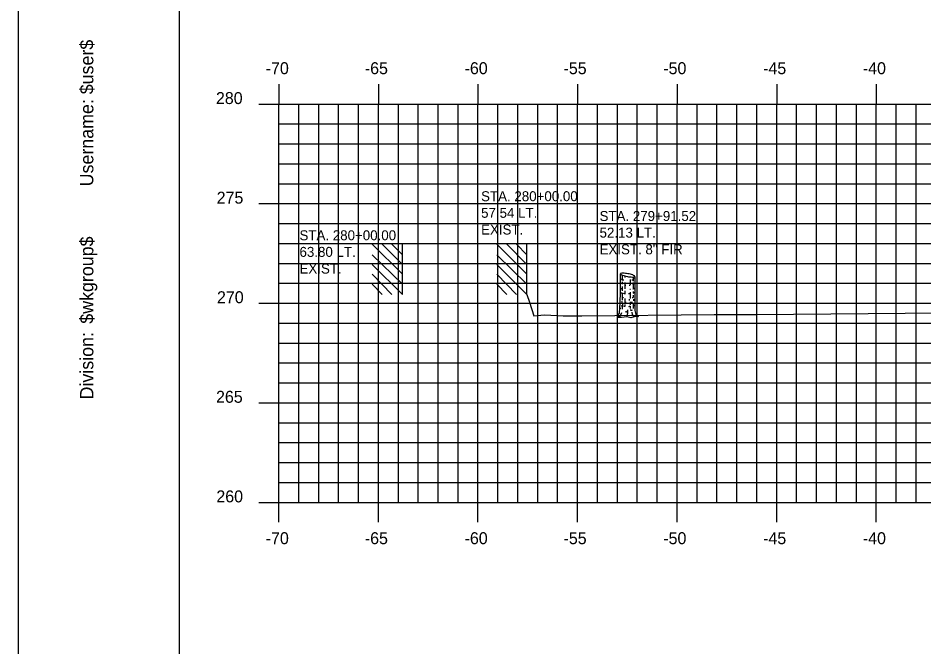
# Model space of a CAD drawing. Extents: x 855121 to 855291, y 366268 to 366378.
# Drawn here: x 855121.35 to 855166.83, y 366299.98 to 366331.55 of the extents above; entities that cross this region are included whole.
import ezdxf

# ---------------------------------------------------------------- set-up
doc = ezdxf.new("R2010")
doc.units = 0
for name, color, linetype in [('BORDER', 7, 'Continuous'), ('D_Text_Monospaced', 7, 'Continuous'), ('H_V ANNOTATION', 7, 'Continuous'), ('MAJOR', 7, 'Continuous'), ('MINOR', 7, 'Continuous'), ('PLOT BOUNDARY', 7, 'Continuous'), ('S_Buildings', 7, 'Continuous'), ('S_Roadway_Centerline', 7, 'Continuous'), ('S_Trees_Conifer_NonPay', 7, 'Continuous')]:
    doc.layers.add(name, color=color, linetype=linetype)

msp = doc.modelspace()

# ---------------------------------------------------------------- linework, layer by layer
at = {"layer": 'BORDER'}
msp.add_line((855129.442, 366376.236), (855129.442, 366271.236), dxfattribs=at)
at = {"layer": 'MAJOR'}
for p, q in [((855134.442, 366328.238), (855134.442, 366327.236)), ((855139.442, 366328.238), (855139.442, 366327.236)), ((855144.442, 366328.238), (855144.442, 366327.236)), ((855149.442, 366328.238), (855149.442, 366327.236)), ((855154.442, 366328.238), (855154.442, 366327.236)), ((855159.442, 366328.238), (855159.442, 366327.236)), ((855164.442, 366328.238), (855164.442, 366327.236)), ((855133.44, 366327.236), (855134.442, 366327.236)), ((855134.442, 366327.236), (855274.442, 366327.236)), ((855134.442, 366307.236), (855134.442, 366327.236)), ((855134.442, 366307.236), (855134.442, 366327.236)), ((855134.442, 366327.236), (855274.442, 366327.236)), ((855139.442, 366307.236), (855139.442, 366327.236)), ((855144.442, 366307.236), (855144.442, 366327.236)), ((855149.442, 366307.236), (855149.442, 366327.236)), ((855154.442, 366307.236), (855154.442, 366327.236)), ((855159.442, 366307.236), (855159.442, 366327.236)), ((855164.442, 366307.236), (855164.442, 366327.236)), ((855133.44, 366322.236), (855134.442, 366322.236)), ((855134.442, 366322.236), (855274.442, 366322.236)), ((855133.44, 366317.236), (855134.442, 366317.236)), ((855134.442, 366317.236), (855274.442, 366317.236)), ((855133.44, 366312.236), (855134.442, 366312.236)), ((855134.442, 366312.236), (855274.442, 366312.236)), ((855133.44, 366307.236), (855134.442, 366307.236)), ((855134.442, 366307.236), (855274.442, 366307.236)), ((855134.442, 366307.236), (855274.442, 366307.236)), ((855134.442, 366306.234), (855134.442, 366307.236)), ((855139.442, 366306.234), (855139.442, 366307.236)), ((855144.442, 366306.234), (855144.442, 366307.236)), ((855149.442, 366306.234), (855149.442, 366307.236)), ((855154.442, 366306.234), (855154.442, 366307.236)), ((855159.442, 366306.234), (855159.442, 366307.236)), ((855164.442, 366306.234), (855164.442, 366307.236))]:
    msp.add_line(p, q, dxfattribs=at)
at = {"layer": 'MINOR'}
for p, q in [((855135.442, 366307.236), (855135.442, 366327.236)), ((855136.442, 366307.236), (855136.442, 366327.236)), ((855137.442, 366307.236), (855137.442, 366327.236)), ((855138.442, 366307.236), (855138.442, 366327.236)), ((855140.442, 366307.236), (855140.442, 366327.236)), ((855141.442, 366307.236), (855141.442, 366327.236)), ((855142.442, 366307.236), (855142.442, 366327.236)), ((855143.442, 366307.236), (855143.442, 366327.236)), ((855145.442, 366307.236), (855145.442, 366327.236)), ((855146.442, 366307.236), (855146.442, 366327.236)), ((855147.442, 366307.236), (855147.442, 366327.236)), ((855148.442, 366307.236), (855148.442, 366327.236)), ((855150.442, 366307.236), (855150.442, 366327.236)), ((855151.442, 366307.236), (855151.442, 366327.236)), ((855152.442, 366307.236), (855152.442, 366327.236)), ((855153.442, 366307.236), (855153.442, 366327.236)), ((855155.442, 366307.236), (855155.442, 366327.236)), ((855156.442, 366307.236), (855156.442, 366327.236)), ((855157.442, 366307.236), (855157.442, 366327.236)), ((855158.442, 366307.236), (855158.442, 366327.236)), ((855160.442, 366307.236), (855160.442, 366327.236)), ((855161.442, 366307.236), (855161.442, 366327.236)), ((855162.442, 366307.236), (855162.442, 366327.236)), ((855163.442, 366307.236), (855163.442, 366327.236)), ((855165.442, 366307.236), (855165.442, 366327.236)), ((855166.442, 366307.236), (855166.442, 366327.236)), ((855134.442, 366326.236), (855274.442, 366326.236)), ((855134.442, 366326.236), (855135.444, 366326.236)), ((855134.442, 366325.236), (855274.442, 366325.236)), ((855134.442, 366325.236), (855135.444, 366325.236)), ((855134.442, 366324.236), (855274.442, 366324.236)), ((855134.442, 366324.236), (855135.444, 366324.236)), ((855134.442, 366323.236), (855274.442, 366323.236)), ((855134.442, 366323.236), (855135.444, 366323.236)), ((855134.442, 366321.236), (855274.442, 366321.236)), ((855134.442, 366321.236), (855135.444, 366321.236)), ((855134.442, 366320.236), (855274.442, 366320.236)), ((855134.442, 366320.236), (855135.444, 366320.236)), ((855134.442, 366319.236), (855274.442, 366319.236)), ((855134.442, 366319.236), (855135.444, 366319.236)), ((855134.442, 366318.236), (855274.442, 366318.236)), ((855134.442, 366318.236), (855135.444, 366318.236)), ((855134.442, 366316.236), (855274.442, 366316.236)), ((855134.442, 366316.236), (855135.444, 366316.236)), ((855134.442, 366315.236), (855274.442, 366315.236)), ((855134.442, 366315.236), (855135.444, 366315.236)), ((855134.442, 366314.236), (855274.442, 366314.236)), ((855134.442, 366314.236), (855135.444, 366314.236)), ((855134.442, 366313.236), (855274.442, 366313.236)), ((855134.442, 366313.236), (855135.444, 366313.236)), ((855134.442, 366311.236), (855274.442, 366311.236)), ((855134.442, 366311.236), (855135.444, 366311.236)), ((855134.442, 366310.236), (855274.442, 366310.236)), ((855134.442, 366310.236), (855135.444, 366310.236)), ((855134.442, 366309.236), (855274.442, 366309.236)), ((855134.442, 366309.236), (855135.444, 366309.236)), ((855134.442, 366308.236), (855274.442, 366308.236)), ((855134.442, 366308.236), (855135.444, 366308.236))]:
    msp.add_line(p, q, dxfattribs=at)
at = {"layer": 'PLOT BOUNDARY'}
msp.add_lwpolyline([(855121.349, 366268.177), (855291.349, 366268.177), (855291.349, 366378.177), (855121.349, 366378.177)], close=True, dxfattribs=at)
at = {"layer": 'S_Buildings'}
for p, q in [((855140.644, 366318.687), (855139.135, 366320.196)), ((855140.644, 366319.179), (855139.627, 366320.196)), ((855140.644, 366319.671), (855140.119, 366320.196)), ((855140.644, 366317.67), (855140.644, 366320.196)), ((855146.902, 366318.688), (855145.393, 366320.197)), ((855146.902, 366319.18), (855145.885, 366320.197)), ((855146.902, 366319.672), (855146.377, 366320.197)), ((855146.902, 366317.671), (855146.902, 366320.197)), ((855140.644, 366318.194), (855139.135, 366319.671)), ((855146.902, 366318.195), (855145.393, 366319.672)), ((855140.644, 366317.67), (855139.135, 366319.179)), ((855146.902, 366317.671), (855145.393, 366319.18)), ((855140.119, 366317.67), (855139.135, 366318.687)), ((855146.377, 366317.671), (855145.393, 366318.688)), ((855139.627, 366317.67), (855139.135, 366318.194)), ((855145.885, 366317.671), (855145.393, 366318.195))]:
    msp.add_line(p, q, dxfattribs=at)
at = {"layer": 'S_Roadway_Centerline'}
msp.add_lwpolyline([(855146.902, 366317.671), (855147.024, 366317.289), (855147.254, 366316.598), (855147.777, 366316.658), (855148.726, 366316.597), (855149.663, 366316.602), (855156.3, 366316.664), (855158.414, 366316.671), (855184.618, 366316.907), (855186.136, 366316.886), (855188.09, 366316.761), (855188.288, 366316.664), (855188.805, 366316.582), (855191.742, 366316.723), (855194.375, 366316.881), (855201.614, 366317.202), (855204.941, 366317.345), (855209.434, 366317.327), (855215.662, 366317.297), (855220.47, 366317.191), (855224.022, 366317.119), (855228.553, 366317.499), (855228.791, 366317.564), (855239.683, 366317.672)], dxfattribs=at)
at = {"layer": 'S_Trees_Conifer_NonPay'}
for p, q in [((855151.815, 366318.605), (855151.815, 366318.527)), ((855152.077, 366318.426), (855152.077, 366318.152)), ((855152.233, 366318.55), (855152.233, 366318.345)), ((855151.68, 366318.317), (855151.68, 366318.186)), ((855151.68, 366318.077), (855151.68, 366317.851)), ((855151.815, 366318.277), (855151.815, 366317.952)), ((855152.233, 366318.272), (855152.233, 366317.941)), ((855151.68, 366317.759), (855151.68, 366317.383)), ((855151.815, 366317.851), (855151.815, 366317.697)), ((855152.077, 366317.798), (855152.077, 366317.48)), ((855152.233, 366317.826), (855152.233, 366317.748)), ((855152.233, 366317.634), (855152.233, 366317.524)), ((855151.699, 366317.19), (855151.682, 366316.945)), ((855151.815, 366317.469), (855151.815, 366317.235)), ((855151.815, 366317.173), (855151.815, 366317.087)), ((855152.035, 366317.435), (855152.035, 366317.366)), ((855152.077, 366317.31), (855152.077, 366317.151)), ((855152.077, 366317.093), (855152.077, 366316.962)), ((855152.233, 366317.235), (855152.233, 366316.968)), ((855152.25, 366317.447), (855152.25, 366317.349)), ((855151.62, 366316.962), (855151.56, 366316.968))]:
    msp.add_line(p, q, dxfattribs=at)
for points in [[(855152.312, 366318.584), (855152.312, 366316.867), (855152.382, 366316.61), (855152.501, 366316.576), (855152.285, 366316.559), (855152.125, 366316.501), (855151.916, 366316.559), (855151.653, 366316.512), (855151.447, 366316.518), (855151.599, 366316.621), (855151.67, 366316.775)], [(855151.569, 366316.601), (855151.453, 366316.61), (855151.545, 366316.735), (855151.579, 366317.276), (855151.599, 366317.793), (855151.599, 366318.712)], [(855151.68, 366318.646), (855151.68, 366318.549), (855151.68, 366318.384)], [(855151.962, 366316.785), (855151.893, 366316.78), (855151.874, 366316.832)], [(855151.916, 366316.559), (855151.96, 366316.735), (855151.966, 366316.9)], [(855152.153, 366316.922), (855152.165, 366316.878), (855152.114, 366316.867), (855152.114, 366316.928)], [(855152.285, 366316.559), (855152.195, 366316.672), (855152.178, 366316.786)]]:
    msp.add_lwpolyline(points, dxfattribs=at)
for centre, radius, start, end in [((855151.613, 366318.71), 0.0141, 153.567, 169.6202), ((855151.613, 366318.71), 0.0141, 169.6202, 185.6733), ((855151.618, 366318.71), 0.0186, 185.6733, 199.6202), ((855151.617, 366318.47), 0.0189, 196.0515, 210), ((855151.625, 366318.713), 0.0263, 199.6202, 218.3805), ((855151.617, 366318.708), 0.0186, 139.6202, 153.567), ((855151.624, 366318.474), 0.0267, 210, 228.7494), ((855151.623, 366318.703), 0.0263, 120.8598, 139.6202), ((855151.661, 366318.742), 0.0729, 218.3805, 229.6202), ((855151.655, 366318.509), 0.0738, 228.7494, 240), ((855151.647, 366318.663), 0.0729, 109.6202, 120.8598), ((855151.773, 366318.873), 0.245, 229.6202, 251.6054), ((855151.74, 366318.657), 0.245, 240, 248.2347), ((855151.705, 366318.501), 0.245, 87.6349, 109.6202), ((855151.74, 366318.657), 0.245, 255.8141, 261.8968), ((855152.272, 366320.373), 1.825, 251.6054, 259.6202), ((855151.955, 366320.165), 1.767, 261.8968, 263.7551), ((855151.64, 366316.922), 1.825, 79.6202, 87.6349), ((855152.272, 366320.373), 1.825, 259.6202, 267.6349), ((855151.64, 366316.922), 1.825, 71.6054, 79.6202), ((855151.955, 366320.165), 1.767, 273.9501, 275.6733), ((855151.955, 366320.165), 1.767, 277.395, 278.1032), ((855152.206, 366318.794), 0.245, 267.6349, 289.6202), ((855152.17, 366318.657), 0.245, 278.1032, 285.1539), ((855152.138, 366318.421), 0.245, 49.6202, 71.6054), ((855152.264, 366318.632), 0.0729, 289.6202, 300.8598), ((855152.25, 366318.553), 0.0729, 38.3805, 49.6202), ((855152.288, 366318.592), 0.0263, 300.8598, 319.6202), ((855152.286, 366318.581), 0.0263, 19.6202, 38.3805), ((855152.294, 366318.587), 0.0186, 319.6202, 333.567), ((855152.294, 366318.584), 0.0186, 5.6733, 19.6202), ((855152.298, 366318.584), 0.0141, 333.567, 349.6202), ((855152.297, 366318.469), 0.0143, 343.9485, 360), ((855152.298, 366318.584), 0.0141, 349.6202, 5.6733), ((855151.615, 366318.218), 0.0189, 196.0515, 210), ((855151.622, 366318.222), 0.0267, 210, 228.7494), ((855151.617, 366318.004), 0.0189, 196.0515, 210), ((855151.624, 366318.008), 0.0267, 210, 228.7494), ((855151.655, 366318.043), 0.0738, 228.7494, 240), ((855151.74, 366318.191), 0.245, 240, 255.8141), ((855151.953, 366319.912), 1.767, 265.5153, 267.2779), ((855151.953, 366319.912), 1.767, 272.4038, 274.1009), ((855151.955, 366319.699), 1.767, 273.8675, 274.7715), ((855152.168, 366318.405), 0.245, 282.4625, 295.6852), ((855152.17, 366318.191), 0.245, 282.4546, 285.1539), ((855152.17, 366318.191), 0.245, 293.2086, 300), ((855152.255, 366318.043), 0.0738, 300, 311.2506), ((855152.286, 366318.008), 0.0267, 311.2506, 330), ((855152.293, 366318.004), 0.0189, 330, 343.9485), ((855152.297, 366318.003), 0.0143, 343.9485, 360), ((855151.617, 366317.793), 0.0189, 196.0515, 210), ((855151.624, 366317.796), 0.0267, 210, 228.7494), ((855151.655, 366317.832), 0.0738, 228.7494, 240), ((855151.74, 366317.98), 0.245, 240, 247.8076), ((855151.741, 366317.76), 0.245, 255.6793, 261.8968), ((855151.956, 366319.268), 1.767, 261.8968, 263.2034), ((855151.955, 366319.487), 1.767, 262.9974, 265.4639), ((855151.955, 366319.487), 1.767, 271.4475, 273.9571), ((855151.956, 366319.268), 1.767, 277.55, 278.1032), ((855152.17, 366317.76), 0.245, 278.1032, 285.0186), ((855152.17, 366317.98), 0.245, 285.0486, 300), ((855152.255, 366317.832), 0.0738, 300, 311.2506), ((855152.286, 366317.796), 0.0267, 311.2506, 330), ((855152.293, 366317.793), 0.0189, 330, 343.9485), ((855152.297, 366317.791), 0.0143, 343.9485, 360), ((855151.656, 366317.19), 0.0738, 237.95, 240), ((855151.742, 366317.338), 0.245, 240, 255.9316), ((855151.741, 366317.543), 0.245, 245.3944, 261.8968), ((855151.956, 366319.051), 1.767, 261.8968, 262.37), ((855151.956, 366318.845), 1.767, 263.6994, 265.7224), ((855151.956, 366319.051), 1.767, 265.4388, 267.3707), ((855151.956, 366318.845), 1.767, 271.7813, 273.9138), ((855151.956, 366319.051), 1.767, 274.9504, 277.7378), ((855152.171, 366317.338), 0.245, 290.8325, 300), ((855152.256, 366317.19), 0.0738, 300, 311.2506), ((855152.287, 366317.154), 0.0267, 311.2506, 330), ((855152.294, 366317.15), 0.0189, 330, 343.9485), ((855152.298, 366317.355), 0.0143, 343.9485, 360), ((855152.298, 366317.149), 0.0143, 343.9485, 360)]:
    msp.add_arc(centre, radius, start, end, dxfattribs=at)

# ---------------------------------------------------------------- texts
at = {"layer": 'BORDER'}
for s, p in [('$user$', (855125.127, 366327.728)), ('Username:', (855125.127, 366323.104)), ('$wkgroup$', (855125.127, 366316.206)), ('Division:', (855125.127, 366312.403))]:
    msp.add_text(s, height=0.6696, rotation=90, dxfattribs=at).set_placement(p)
at = {"layer": 'D_Text_Monospaced'}
for s, height, p in [('STA. 280+00.00', 0.49998, (855144.598, 366322.359)), ('57.54 LT.', 0.5, (855144.598, 366321.525)), ('STA. 279+91.52', 0.49998, (855150.546, 366321.365)), ('EXIST. ', 0.5, (855144.598, 366320.685)), ('STA. 280+00.00', 0.49998, (855135.479, 366320.397)), ('52.13 LT.', 0.5, (855150.546, 366320.531)), ('63.80 LT.', 0.5, (855135.479, 366319.563)), ('EXIST. 8" FIR', 0.49998, (855150.546, 366319.691)), ('EXIST. ', 0.5, (855135.479, 366318.723))]:
    msp.add_text(s, height=height, dxfattribs=at).set_placement(p)
at = {"layer": 'H_V ANNOTATION'}
for s, p in [('-70', (855133.783, 366328.736)), ('-65', (855138.76, 366328.736)), ('-60', (855143.768, 366328.736)), ('-55', (855148.738, 366328.736)), ('-50', (855153.746, 366328.736)), ('-45', (855158.76, 366328.736)), ('-40', (855163.768, 366328.736)), ('280', (855131.283, 366327.236)), ('275', (855131.32, 366322.236)), ('270', (855131.336, 366317.236)), ('265', (855131.288, 366312.236)), ('260', (855131.304, 366307.236)), ('-70', (855133.783, 366305.136)), ('-65', (855138.76, 366305.136)), ('-60', (855143.768, 366305.136)), ('-55', (855148.738, 366305.136)), ('-50', (855153.746, 366305.136)), ('-45', (855158.76, 366305.136)), ('-40', (855163.768, 366305.136))]:
    msp.add_text(s, height=0.6, dxfattribs=at).set_placement(p)

doc.saveas('drawing.dxf')
